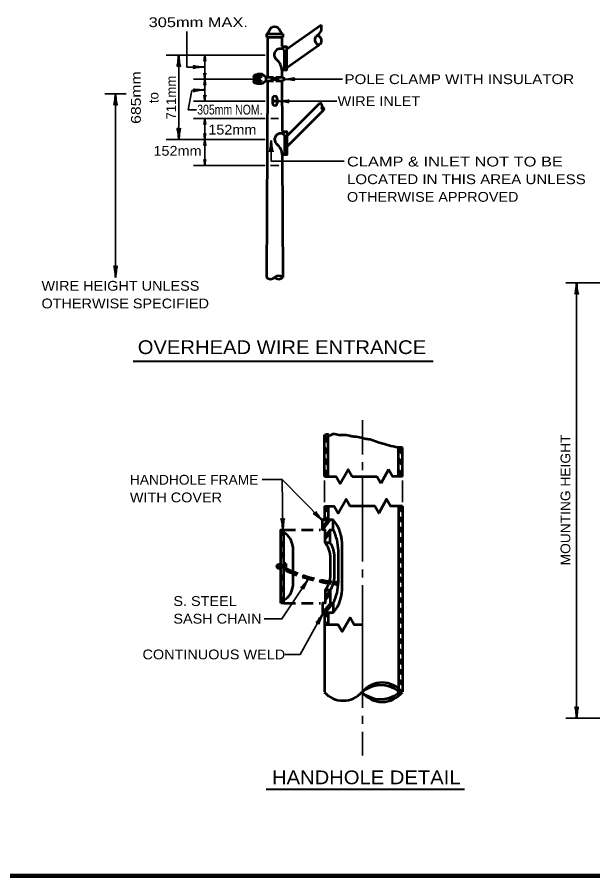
# Model space of a CAD drawing. Extents: x -32 to 824, y -12 to 532.
# Drawn here: x 256.9 to 433, y -0.9 to 261.8 of the extents above; entities that cross this region are included whole.
import ezdxf
from ezdxf.enums import TextEntityAlignment as Align

# ---------------------------------------------------------------- set-up
doc = ezdxf.new("R2010")
doc.units = 0
doc.header["$LTSCALE"] = 1.2
doc.linetypes.add('MEDIUM_DASHED', pattern=[4.5, 3, -1.5])
doc.layers.add('1', color=7, linetype='Continuous', lineweight=13)

msp = doc.modelspace()

# ---------------------------------------------------------------- hatches: boundary and pattern name
at = {"layer": '1'}
h = msp.add_hatch(color=256, dxfattribs=at)
edge = h.paths.add_edge_path()
edge.add_ellipse((330.389, 243.583), major_axis=(1.08, 0), ratio=0.6666667, start_angle=0, end_angle=360)
h = msp.add_hatch(color=256, dxfattribs=at)
edge = h.paths.add_edge_path()
edge.add_ellipse((330.389, 242.091), major_axis=(1.08, 0), ratio=0.6666667, start_angle=0, end_angle=360)
msp.add_hatch(color=256, dxfattribs=at).paths.add_polyline_path([(337.659, 93.765, 1), (336.352, 93.765, 1)])

# ---------------------------------------------------------------- linework, layer by layer
at = {"layer": '1', "lineweight": 53}
for p, q in [((339.246, 252.017), (349.863, 259.451)), ((333.112, 256.697), (338.152, 256.697)), ((333.112, 256.697), (333.112, 255.617)), ((333.112, 255.617), (338.152, 255.617)), ((333.472, 255.617), (333.412, 243.377)), ((337.792, 255.617), (337.806, 252.737)), ((338.152, 256.697), (338.152, 255.617)), ((338.166, 252.737), (338.166, 251.898)), ((339.246, 246.257), (349.273, 253.278)), ((338.526, 251.657), (338.526, 245.537)), ((331.829, 244.303), (330.389, 244.303)), ((332.932, 243.377), (331.829, 244.303)), ((337.841, 245.537), (337.852, 243.377)), ((332.932, 242.297), (331.829, 241.371)), ((332.932, 243.377), (335.272, 243.377)), ((332.932, 243.377), (332.932, 242.297)), ((332.932, 242.297), (335.272, 242.297)), ((333.407, 242.297), (333.112, 182.177)), ((334.696, 243.377), (334.696, 242.297)), ((335.272, 243.377), (335.272, 242.297)), ((335.992, 243.377), (338.332, 243.377)), ((335.992, 243.377), (335.992, 242.297)), ((335.992, 242.297), (338.332, 242.297)), ((336.568, 243.377), (336.568, 242.297)), ((337.857, 242.297), (337.933, 226.817)), ((338.332, 243.377), (338.332, 242.297)), ((331.829, 241.371), (330.389, 241.371)), ((335.004, 236.883), (335.011, 235.443)), ((336.444, 236.89), (336.451, 235.45)), ((339.374, 225.377), (349.556, 235.56)), ((339.374, 222.137), (350.574, 233.338)), ((338.293, 226.817), (338.293, 225.978)), ((338.654, 225.737), (338.654, 219.617)), ((337.969, 219.617), (338.152, 182.177)), ((350.847, 121.262), (350.847, 133.982)), ((352.047, 121.262), (352.047, 133.982)), ((352.047, 132.398), (350.847, 133.598)), ((352.047, 131.534), (350.847, 132.734)), ((352.047, 128.966), (350.847, 130.166)), ((352.047, 128.102), (350.847, 129.326)), ((373.527, 121.262), (373.527, 130.166)), ((374.727, 128.966), (373.527, 130.166)), ((374.727, 128.102), (373.527, 129.326)), ((374.727, 121.262), (374.727, 130.166)), ((352.047, 125.558), (350.847, 126.758)), ((374.727, 125.558), (373.527, 126.758)), ((352.047, 124.694), (350.847, 125.894)), ((374.727, 124.694), (373.527, 125.894)), ((352.047, 122.126), (350.847, 123.326)), ((352.047, 121.262), (350.847, 122.486)), ((359.319, 121.262), (366.879, 121.262)), ((368.079, 119.174), (366.879, 121.262)), ((370.503, 123.374), (368.079, 119.174)), ((374.727, 122.126), (373.527, 123.326)), ((374.727, 121.262), (373.527, 122.486)), ((350.847, 112.19), (352.047, 111.206)), ((350.847, 112.19), (350.847, 107.966)), ((350.847, 111.422), (352.047, 110.414)), ((352.047, 112.19), (352.047, 107.966)), ((373.527, 112.19), (374.727, 111.206)), ((373.527, 111.422), (374.727, 110.414)), ((374.727, 112.19), (374.727, 55.358)), ((352.647, 107.966), (350.247, 104.942)), ((351.879, 107.966), (350.247, 105.902)), ((350.247, 107.966), (352.647, 107.966)), ((350.847, 109.07), (352.047, 108.062)), ((350.847, 108.278), (351.231, 107.966)), ((353.559, 107.966), (351.135, 107.966)), ((373.527, 109.07), (374.727, 108.062)), ((373.527, 108.278), (374.727, 107.294)), ((352.647, 105.062), (351.135, 103.166)), ((373.527, 105.926), (374.727, 104.942)), ((373.527, 105.134), (374.727, 104.15)), ((338.439, 103.934), (337.527, 104.846)), ((338.439, 103.094), (337.527, 104.006)), ((338.439, 82.574), (338.439, 104.942)), ((352.647, 104.102), (351.135, 102.206)), ((373.527, 102.782), (374.727, 101.798)), ((338.439, 100.526), (337.527, 101.438)), ((338.439, 99.662), (337.527, 100.574)), ((341.175, 99.806), (341.175, 87.71)), ((352.647, 101.006), (351.135, 101.006)), ((356.343, 87.71), (356.343, 99.806)), ((373.527, 102.014), (374.727, 101.006)), ((338.439, 97.094), (337.527, 98.006)), ((353.919, 90.134), (353.919, 97.382)), ((355.143, 88.91), (355.143, 98.582)), ((373.527, 99.662), (374.727, 98.654)), ((373.527, 98.87), (374.727, 97.886)), ((338.439, 96.254), (337.527, 97.166)), ((339.039, 94.67), (338.439, 94.67)), ((338.583, 94.67), (338.583, 92.846)), ((338.679, 94.67), (338.679, 92.846)), ((338.679, 94.67), (338.679, 92.846)), ((338.775, 94.67), (338.775, 92.846)), ((338.775, 94.67), (338.775, 92.846)), ((338.847, 94.67), (338.847, 92.846)), ((338.919, 94.67), (338.919, 92.846)), ((338.943, 94.67), (338.943, 92.846)), ((338.991, 94.67), (338.991, 92.846)), ((339.039, 94.67), (339.039, 92.846)), ((352.719, 91.334), (352.719, 96.182)), ((373.527, 96.518), (374.727, 95.534)), ((373.527, 95.75), (374.727, 94.742)), ((338.439, 94.046), (337.527, 94.046)), ((338.439, 93.902), (337.527, 93.902)), ((338.439, 93.806), (337.527, 93.806)), ((338.439, 93.806), (337.527, 93.806)), ((338.439, 93.662), (337.527, 93.662)), ((338.439, 93.518), (337.527, 93.518)), ((338.439, 93.446), (337.527, 93.446)), ((339.039, 92.846), (338.439, 92.846)), ((373.527, 93.398), (374.727, 92.39)), ((373.527, 92.606), (374.727, 91.598)), ((338.439, 90.254), (337.527, 91.166)), ((338.439, 89.414), (337.527, 90.302)), ((373.527, 90.638), (374.727, 89.654)), ((373.527, 89.87), (374.727, 88.862)), ((338.439, 86.846), (337.527, 87.758)), ((338.439, 85.982), (337.527, 86.894)), ((373.527, 87.518), (374.727, 86.51)), ((373.527, 86.726), (374.727, 85.742)), ((338.439, 83.414), (337.527, 84.326)), ((352.647, 86.342), (351.135, 84.446)), ((352.647, 85.358), (351.135, 83.486)), ((373.527, 84.374), (374.727, 83.39)), ((338.439, 82.574), (337.527, 83.462)), ((338.439, 82.574), (337.527, 82.574)), ((352.743, 82.574), (350.319, 79.55)), ((353.559, 82.622), (351.087, 79.55)), ((373.527, 83.582), (374.727, 82.598)), ((350.247, 79.55), (352.647, 79.55)), ((350.847, 79.55), (350.847, 75.902)), ((350.847, 79.238), (352.047, 78.23)), ((353.559, 79.55), (351.135, 79.55)), ((351.423, 79.55), (352.047, 79.022)), ((352.047, 79.55), (352.047, 75.902)), ((373.527, 81.23), (374.727, 80.246)), ((373.527, 80.462), (374.727, 79.454)), ((350.847, 76.886), (352.023, 75.902)), ((373.527, 78.11), (374.727, 77.102)), ((373.527, 77.318), (374.727, 76.334)), ((350.847, 76.094), (351.063, 75.902)), ((373.527, 74.966), (374.727, 73.982)), ((373.527, 74.198), (374.727, 73.19)), ((373.527, 71.846), (374.727, 70.838)), ((373.527, 71.054), (374.727, 70.046)), ((373.527, 68.702), (374.727, 67.694)), ((373.527, 67.91), (374.727, 66.926)), ((373.527, 65.558), (374.727, 64.574)), ((373.527, 64.79), (374.727, 63.782)), ((373.527, 62.438), (374.727, 61.43)), ((373.527, 61.646), (374.727, 60.662)), ((366.255, 57.878), (366.519, 57.278)), ((373.527, 59.294), (374.727, 58.31)), ((373.527, 58.502), (374.727, 57.518)), ((365.679, 57.686), (365.919, 57.158)), ((371.175, 57.758), (370.815, 56.99)), ((371.727, 57.542), (371.391, 56.774)), ((373.167, 54.782), (374.583, 55.166)), ((373.527, 55.502), (374.295, 55.718)), ((365.895, 52.79), (366.159, 53.342)), ((366.471, 52.622), (366.759, 53.246)), ((370.959, 52.718), (370.599, 53.51)), ((371.535, 52.934), (371.175, 53.702))]:
    msp.add_line(p, q, dxfattribs=at)
at = {"layer": '1', "lineweight": 35}
for p, q in [((302.464, 250.18), (332.726, 250.18)), ((306.307, 250.18), (306.307, 224.304)), ((310.865, 242.823), (329.267, 242.823)), ((338.332, 242.8), (356.426, 242.8)), ((310.292, 239.346), (309.221, 233.378)), ((310.292, 239.346), (314.179, 239.536)), ((290.267, 238.275), (283.667, 238.275)), ((286.967, 238.275), (286.967, 182.177)), ((310.865, 236.1), (332.726, 236.1)), ((336.61, 236.064), (354.704, 236.064)), ((311.718, 233.378), (309.221, 233.378)), ((310.865, 230.773), (332.726, 230.773)), ((334.431, 230.777), (336.834, 230.777)), ((302.464, 224.304), (332.726, 224.304)), ((310.865, 216.375), (332.726, 216.375)), ((334.36, 216.377), (336.905, 216.377)), ((446.828, 180.505), (424.689, 180.505)), ((428.027, 180.505), (428.027, 47.305)), ((362.487, 128.03), (362.487, 138.518)), ((362.487, 125.63), (362.487, 123.206)), ((362.487, 121.262), (362.487, 116.75)), ((337.954, 120.394), (331.804, 120.394)), ((350.847, 113.414), (350.847, 120.062)), ((362.487, 120.782), (362.487, 95.27)), ((374.727, 113.414), (374.727, 120.062)), ((362.487, 92.846), (362.487, 90.422)), ((362.487, 87.998), (362.487, 50.462)), ((362.487, 48.038), (362.487, 45.614)), ((446.828, 47.305), (424.689, 47.305)), ((362.487, 43.214), (362.487, 35.966))]:
    msp.add_line(p, q, dxfattribs=at)
at = {"layer": '1', "lineweight": 40}
for p, q in [((292.315, 156.544), (384.149, 156.544)), ((333.068, 25.653), (393.732, 25.653))]:
    msp.add_line(p, q, dxfattribs=at)
at = {"layer": '1', "linetype": 'MEDIUM_DASHED', "lineweight": 53}
for p, q in [((338.439, 104.942), (349.623, 104.942)), ((338.439, 82.574), (349.623, 82.574))]:
    msp.add_line(p, q, dxfattribs=at)
at = {"layer": '1', "lineweight": 158}
msp.add_line((817.469, -0.873), (25.869, -0.873), dxfattribs=at)
at = {"layer": '1', "lineweight": 35}
for points in [[(314.225, 246.5), (308.782, 246.5), (308.782, 257.389)], [(314.299, 250.18), (314.299, 242.823), (314.299, 236.1)], [(314.299, 230.773), (314.299, 224.304), (314.299, 216.375)], [(334.605, 224.051), (334.605, 217.698), (356.86, 217.698)], [(350.247, 107.76), (337.954, 120.394), (338.138, 104.942)], [(345.973, 89.946), (337.853, 77.728), (332.487, 77.728)], [(350.418, 79.379), (343.424, 66.855), (338.736, 66.855)]]:
    msp.add_lwpolyline(points, dxfattribs=at)
at = {"layer": '1', "lineweight": 53}
for points in [[(337.806, 252.737), (339.246, 252.737), (339.246, 245.537), (337.841, 245.537)], [(337.933, 226.817), (339.374, 226.817), (339.374, 219.617), (337.969, 219.617)], [(350.847, 121.262), (354.471, 121.262), (355.671, 119.174), (358.095, 123.374), (359.319, 121.262)], [(374.727, 121.262), (371.703, 121.262), (370.503, 123.374)], [(350.847, 112.19), (353.871, 112.19), (355.071, 110.102), (357.495, 114.302), (358.695, 112.19)], [(374.727, 112.19), (371.103, 112.19), (369.903, 114.302), (367.479, 110.102), (366.255, 112.19), (358.695, 112.19)], [(373.527, 112.19), (373.527, 87.662), (373.527, 56.438)], [(351.135, 101.006), (351.135, 104.942), (350.247, 104.942), (350.247, 107.966)], [(351.135, 101.006), (352.647, 101.006), (352.647, 104.942), (353.559, 104.942), (353.559, 107.966)], [(337.527, 82.574), (337.527, 104.942), (338.439, 104.942)], [(352.647, 86.486), (351.135, 86.486), (351.135, 82.574), (350.247, 82.574), (350.247, 79.55)], [(351.135, 86.486), (352.647, 86.486), (352.647, 82.574), (353.559, 82.574), (353.559, 79.55)], [(362.343, 75.902), (359.919, 75.902), (358.695, 78.014), (356.295, 73.814), (355.071, 75.902), (350.847, 75.902), (350.847, 55.358)]]:
    msp.add_lwpolyline(points, dxfattribs=at)
for points in [[(350.247, 107.966), (350.847, 108.566), (350.847, 107.966)], [(350.247, 79.55), (350.847, 78.95), (350.847, 79.55)]]:
    msp.add_lwpolyline(points, close=True, dxfattribs=at)
for centre, radius in [((337.006, 93.765), 0.654), ((354.431, 88.624), 0.454)]:
    msp.add_circle(centre, radius, dxfattribs=at)
for centre, radius, start, end in [((332.882, 257.787), 1.114, 281.94387, 347.91984), ((335.632, 257.071), 1.73, 16.19781, 163.80219), ((338.383, 257.787), 1.114, 192.08016, 258.05613), ((347.332, 258.525), 2.695, 295.32486, 20.09191), ((337.337, 250.27), 1.827, 49.39069, 236.15933), ((333.109, 245.264), 4.741, 3.29768, 47.3671), ((335.724, 236.904), 0.72, 358.85054, 181.71286), ((335.731, 235.464), 0.72, 358.85054, 181.71286), ((335.731, 235.421), 0.72, 178.28714, 1.14946), ((349.215, 234.611), 1.008, 339.80476, 70.23541), ((337.464, 224.35), 1.827, 49.39069, 236.15933), ((333.236, 219.344), 4.741, 3.29768, 47.3671), ((334.372, 183.488), 1.818, 226.13133, 313.86868), ((336.892, 180.866), 1.818, 46.13132, 133.86867), ((336.892, 183.488), 1.818, 226.13133, 313.86868), ((344.683, 100.385), 11.675, 357.13004, 40.48815), ((336.239, 99.626), 4.928, 2.02606, 63.44439), ((340.967, 98.455), 14.167, 0.54939, 27.24732), ((344.336, 96.124), 8.379, 0.31998, 35.66459), ((345.362, 96.423), 8.616, 6.38376, 32.16514), ((344.336, 91.38), 8.379, 324.33541, 359.68002), ((345.362, 91.081), 8.616, 327.83486, 353.61624), ((336.239, 87.878), 4.928, 296.55561, 357.97394), ((340.967, 89.092), 14.167, 332.75268, 359.45061), ((344.683, 87.162), 11.675, 319.51185, 2.86996), ((368.531, 50.331), 7.891, 38.8447, 141.1553), ((356.586, 60.291), 7.58, 220.71167, 319.28832), ((368.101, 48.817), 8.613, 51.54154, 132.04732), ((368.531, 60.229), 7.891, 218.22248, 321.77751), ((368.101, 61.743), 8.613, 227.95268, 308.4983), ((373.245, 55.282), 0.353, 307.8273, 52.77092)]:
    msp.add_arc(centre, radius, start, end, dxfattribs=at)
at = {"layer": '1', "linetype": 'MEDIUM_DASHED', "lineweight": 53}
for centre, radius, start, end in [((359.076, 135.955), 47.535, 245.08086, 263.60629), ((358.457, 134.1), 45.885, 245.04728, 263.19799), ((358.054, 132.66), 43.802, 244.77769, 263.49597)]:
    msp.add_arc(centre, radius, start, end, dxfattribs=at)
at = {"layer": '1', "lineweight": 53}
for centre, major_axis, ratio in [((348.951, 254.701), (-0.322, 1.424), 0.618585), ((330.389, 243.583), (1.08, 0), 0.666667), ((330.389, 242.091), (1.08, 0), 0.666667), ((350.383, 233.805), (-0.191, 0.468), 0.505648)]:
    msp.add_ellipse(centre, major_axis=major_axis, ratio=ratio, dxfattribs=at)
at = {"layer": '1', "lineweight": 40}
for centre, major_axis, ratio, start_param, end_param in [((306.053, 248.824), (0.211, 2.108), 0.07063, 3.1407148, 5.41811), ((306.639, 248.859), (-0.187, 2.143), 0.122415, 0.8963533, 3.1415927), ((314.049, 248.824), (0.211, 2.108), 0.07063, 4.7093373, 5.41811), ((314.635, 248.859), (-0.187, 2.143), 0.122415, 0.8963533, 1.5837952), ((312.88, 246.754), (2.108, -0.211), 0.07063, 3.1407148, 5.41811), ((314.266, 250.441), (0.211, 2.108), 0.07063, 3.1407148, 3.8293255), ((314.4, 250.464), (-0.187, 2.143), 0.122415, 2.4431075, 3.1415927), ((312.916, 246.168), (2.143, 0.187), 0.122415, 0.8963533, 3.1415927), ((314.252, 242.561), (0.211, -2.108), 0.07063, 2.4538598, 3.1424706), ((314.387, 242.538), (-0.187, -2.143), 0.122415, 3.1415927, 3.8400778), ((314.036, 244.178), (0.211, -2.108), 0.07063, 0.8650754, 1.573848), ((314.049, 241.467), (0.211, 2.108), 0.07063, 4.7093373, 5.41811), ((314.621, 244.143), (-0.187, -2.143), 0.122415, 4.6993901, 5.386832), ((314.635, 241.502), (-0.187, 2.143), 0.122415, 0.8963533, 1.5837952), ((339.688, 242.537), (-2.108, 0.211), 0.07063, 3.1407148, 5.41811), ((339.653, 243.122), (-2.143, -0.187), 0.122415, 0.8963533, 3.1415927), ((312.824, 239.724), (2.115, -0.108), 0.07063, 3.1407148, 5.41811), ((312.887, 239.141), (2.131, 0.291), 0.122415, 0.8963533, 3.1415927), ((314.266, 243.084), (0.211, 2.108), 0.07063, 3.1407148, 3.8293255), ((314.4, 243.107), (-0.187, 2.143), 0.122415, 2.4431075, 3.1415927), ((286.713, 236.93), (0.211, 2.108), 0.07063, 3.1407148, 5.41811), ((287.299, 236.965), (-0.187, 2.143), 0.122415, 0.8963533, 3.1415927), ((314.252, 235.839), (0.211, -2.108), 0.07063, 2.4538598, 3.1424706), ((314.036, 237.456), (0.211, -2.108), 0.07063, 0.8650754, 1.573848), ((314.621, 237.42), (-0.187, -2.143), 0.122415, 4.6993901, 5.386832), ((314.387, 235.815), (-0.187, -2.143), 0.122415, 3.1415927, 3.8400778), ((337.931, 236.386), (-2.143, -0.187), 0.122415, 0.8963533, 3.1415927), ((337.966, 235.8), (-2.108, 0.211), 0.07063, 3.1407148, 5.41811), ((314.266, 231.034), (0.211, 2.108), 0.07063, 3.1407148, 3.8293255), ((314.049, 229.417), (0.211, 2.108), 0.07063, 4.7093373, 5.41811), ((314.635, 229.452), (-0.187, 2.143), 0.122415, 0.8963533, 1.5837952), ((314.4, 231.057), (-0.187, 2.143), 0.122415, 2.4431075, 3.1415927), ((305.985, 225.624), (0.187, -2.143), 0.122415, 0.8963533, 3.1415927), ((306.571, 225.659), (-0.211, -2.108), 0.07063, 3.1407148, 5.41811), ((314.252, 224.042), (0.211, -2.108), 0.07063, 2.4538598, 3.1424706), ((314.387, 224.019), (-0.187, -2.143), 0.122415, 3.1415927, 3.8400778), ((314.036, 225.659), (0.211, -2.108), 0.07063, 0.8650754, 1.573848), ((314.049, 222.948), (0.211, 2.108), 0.07063, 4.7093373, 5.41811), ((314.621, 225.624), (-0.187, -2.143), 0.122415, 4.6993901, 5.386832), ((314.635, 222.983), (-0.187, 2.143), 0.122415, 0.8963533, 1.5837952), ((334.351, 222.706), (0.211, 2.108), 0.07063, 3.1407148, 5.41811), ((334.936, 222.741), (-0.187, 2.143), 0.122415, 0.8963533, 3.1415927), ((314.266, 224.565), (0.211, 2.108), 0.07063, 3.1407148, 3.8293255), ((314.4, 224.588), (-0.187, 2.143), 0.122415, 2.4431075, 3.1415927), ((314.252, 216.113), (0.211, -2.108), 0.07063, 2.4538598, 3.1424706), ((314.387, 216.09), (-0.187, -2.143), 0.122415, 3.1415927, 3.8400778), ((314.036, 217.73), (0.211, -2.108), 0.07063, 0.8650754, 1.573848), ((314.621, 217.695), (-0.187, -2.143), 0.122415, 4.6993901, 5.386832), ((286.645, 183.497), (0.187, -2.143), 0.122415, 0.8963533, 3.1415927), ((287.231, 183.532), (-0.211, -2.108), 0.07063, 3.1407148, 5.41811), ((427.773, 179.161), (0.211, 2.108), 0.07063, 3.1407148, 5.41811), ((428.358, 179.196), (-0.187, 2.143), 0.122415, 0.8963533, 3.1415927), ((349.491, 108.901), (-1.319, 1.658), 0.07063, 6.2823074, 8.5597026), ((349.491, 108.901), (-1.319, 1.658), 0.07063, 6.2823074, 8.5597026), ((337.791, 106.248), (0.213, -2.14), 0.122415, 0.8963533, 3.1415927), ((337.791, 106.248), (0.213, -2.14), 0.122415, 0.8963533, 3.1415927), ((338.376, 106.29), (-0.186, -2.11), 0.07063, 3.1407148, 5.41811), ((338.376, 106.29), (-0.186, -2.11), 0.07063, 3.1407148, 5.41811), ((349.096, 108.467), (1.629, -1.405), 0.122415, 0.8963533, 3.1415927), ((349.096, 108.467), (1.629, -1.405), 0.122415, 0.8963533, 3.1415927), ((345.017, 88.967), (-1.342, -1.639), 0.07063, 6.2823074, 8.5597026), ((345.017, 88.967), (-1.342, -1.639), 0.07063, 6.2823074, 8.5597026), ((345.524, 88.672), (1.03, 1.888), 0.122415, 0.8963533, 3.1415927), ((345.524, 88.672), (1.03, 1.888), 0.122415, 0.8963533, 3.1415927), ((349.541, 78.329), (1.212, 1.737), 0.07063, 3.1407148, 5.41811), ((349.541, 78.329), (1.212, 1.737), 0.07063, 3.1407148, 5.41811), ((350.069, 78.074), (0.881, 1.962), 0.122415, 0.8963533, 3.1415927), ((350.069, 78.074), (0.881, 1.962), 0.122415, 0.8963533, 3.1415927), ((427.695, 48.615), (0.187, -2.143), 0.122415, 0.8963533, 3.1415927), ((428.281, 48.65), (-0.211, -2.108), 0.07063, 3.1407148, 5.41811)]:
    msp.add_ellipse(centre, major_axis=major_axis, ratio=ratio, start_param=start_param, end_param=end_param, dxfattribs=at)
at = {"layer": '1', "lineweight": 53}
for points in [[(350.847, 133.982), (351.351, 134.15), (351.879, 134.222), (352.047, 133.982), (353.583, 134.318), (355.239, 133.982), (356.439, 134.03), (358.551, 133.79), (359.511, 133.574), (361.095, 133.43), (363.207, 132.902), (364.815, 132.638), (367.095, 131.846), (369.231, 131.222), (371.895, 130.502), (373.527, 130.166)], [(373.071, 130.262), (374.103, 130.238), (374.727, 130.166)]]:
    msp.add_spline(points, degree=3, dxfattribs=at)

# ---------------------------------------------------------------- texts
at = {"layer": '1'}
for s, height, width, p in [('305mm MAX.', 3, 1.25, (297.092, 258.713)), ('POLE CLAMP WITH INSULATOR', 3, 1.15, (357.022, 241.289)), ('WIRE INLET', 3, 1.1, (354.915, 234.592)), ('305mm NOM.', 3, 0.8, (311.952, 231.983)), ('CLAMP & INLET NOT TO BE', 3, 1.25, (357.768, 216.09)), ('LOCATED IN THIS AREA UNLESS', 3, 1.15, (357.768, 210.69)), ('OTHERWISE APPROVED', 3, 1.1, (357.768, 205.29)), ('WIRE HEIGHT UNLESS', 3, 1.1, (264.318, 178.089)), ('OTHERWISE SPECIFIED', 3, 1.1, (264.318, 172.689)), ('OVERHEAD WIRE ENTRANCE', 4.2, 1.1, (293.767, 158.722)), ('HANDHOLE FRAME', 3, 1.05, (291.355, 118.772)), ('WITH COVER', 3, 1.1, (291.355, 113.372)), ('S. STEEL', 3, 1.1, (304.663, 81.669)), ('SASH CHAIN', 3, 1.1, (304.663, 76.269)), ('CONTINUOUS WELD', 3, 1.1, (295.218, 65.344)), ('HANDHOLE DETAIL', 4.2, 1.1, (334.834, 27.148))]:
    msp.add_text(s, height=height, dxfattribs=dict(at, width=width)).set_placement(p)
at = {"layer": '1', "width": 1.2}
msp.add_text('685mm', height=3, rotation=90, dxfattribs=at).set_placement((294.7, 237.154), align=Align.CENTER)
at = {"layer": '1'}
for s, p in [('711mm', (305.5, 237.154)), ('to', (300.1, 237.153))]:
    msp.add_text(s, height=3, rotation=90, dxfattribs=at).set_placement(p, align=Align.CENTER)
at = {"layer": '1', "width": 1.1}
for p in [(322.703, 225.858), (305.924, 219.375)]:
    msp.add_text('152mm', height=3, dxfattribs=at).set_placement(p, align=Align.CENTER)
at = {"layer": '1', "width": 1.05}
msp.add_text('MOUNTING HEIGHT', height=3, rotation=90, dxfattribs=at).set_placement((426.108, 94.081))

doc.saveas('drawing.dxf')
